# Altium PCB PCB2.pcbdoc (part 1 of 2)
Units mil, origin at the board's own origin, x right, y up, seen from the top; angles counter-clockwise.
Board outline 2299 x 1559.01 mil, 4 copper layers (Top Layer, Inner1, Inner2, Bottom Layer); 35 components, 78 nets, 930 pads, 283 vias.
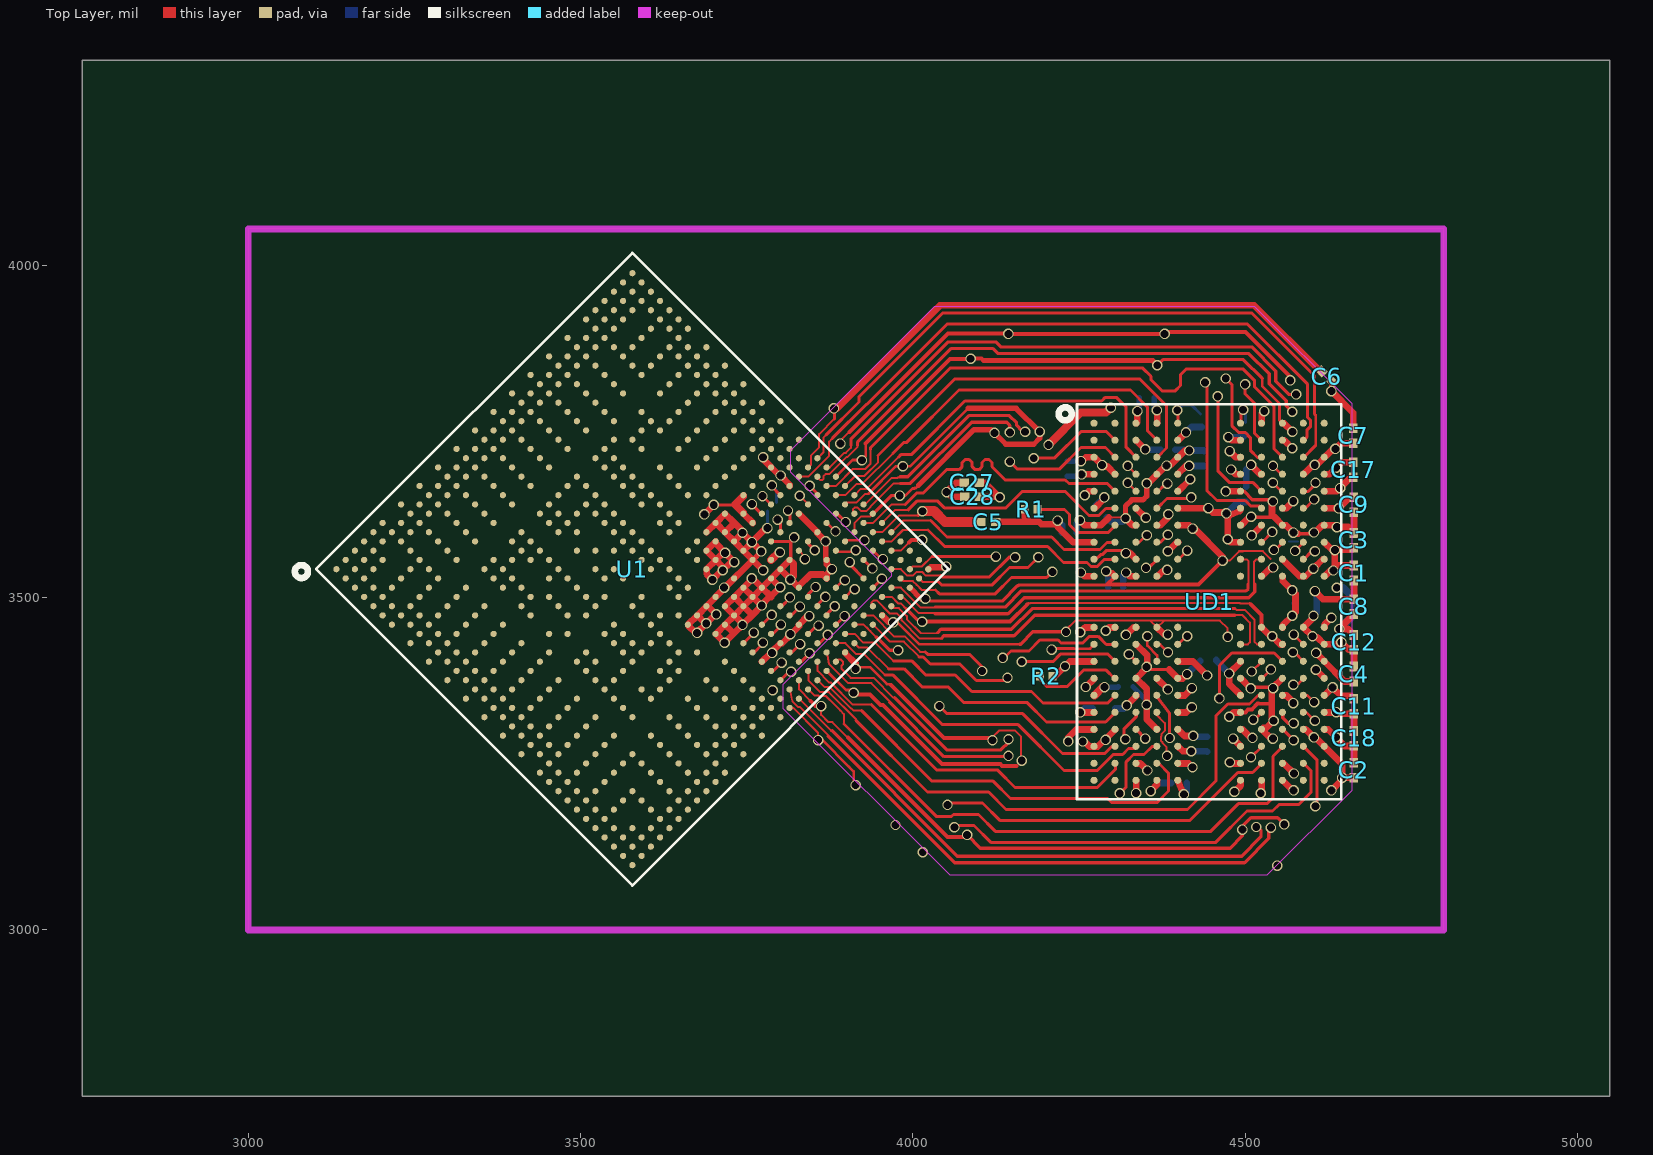
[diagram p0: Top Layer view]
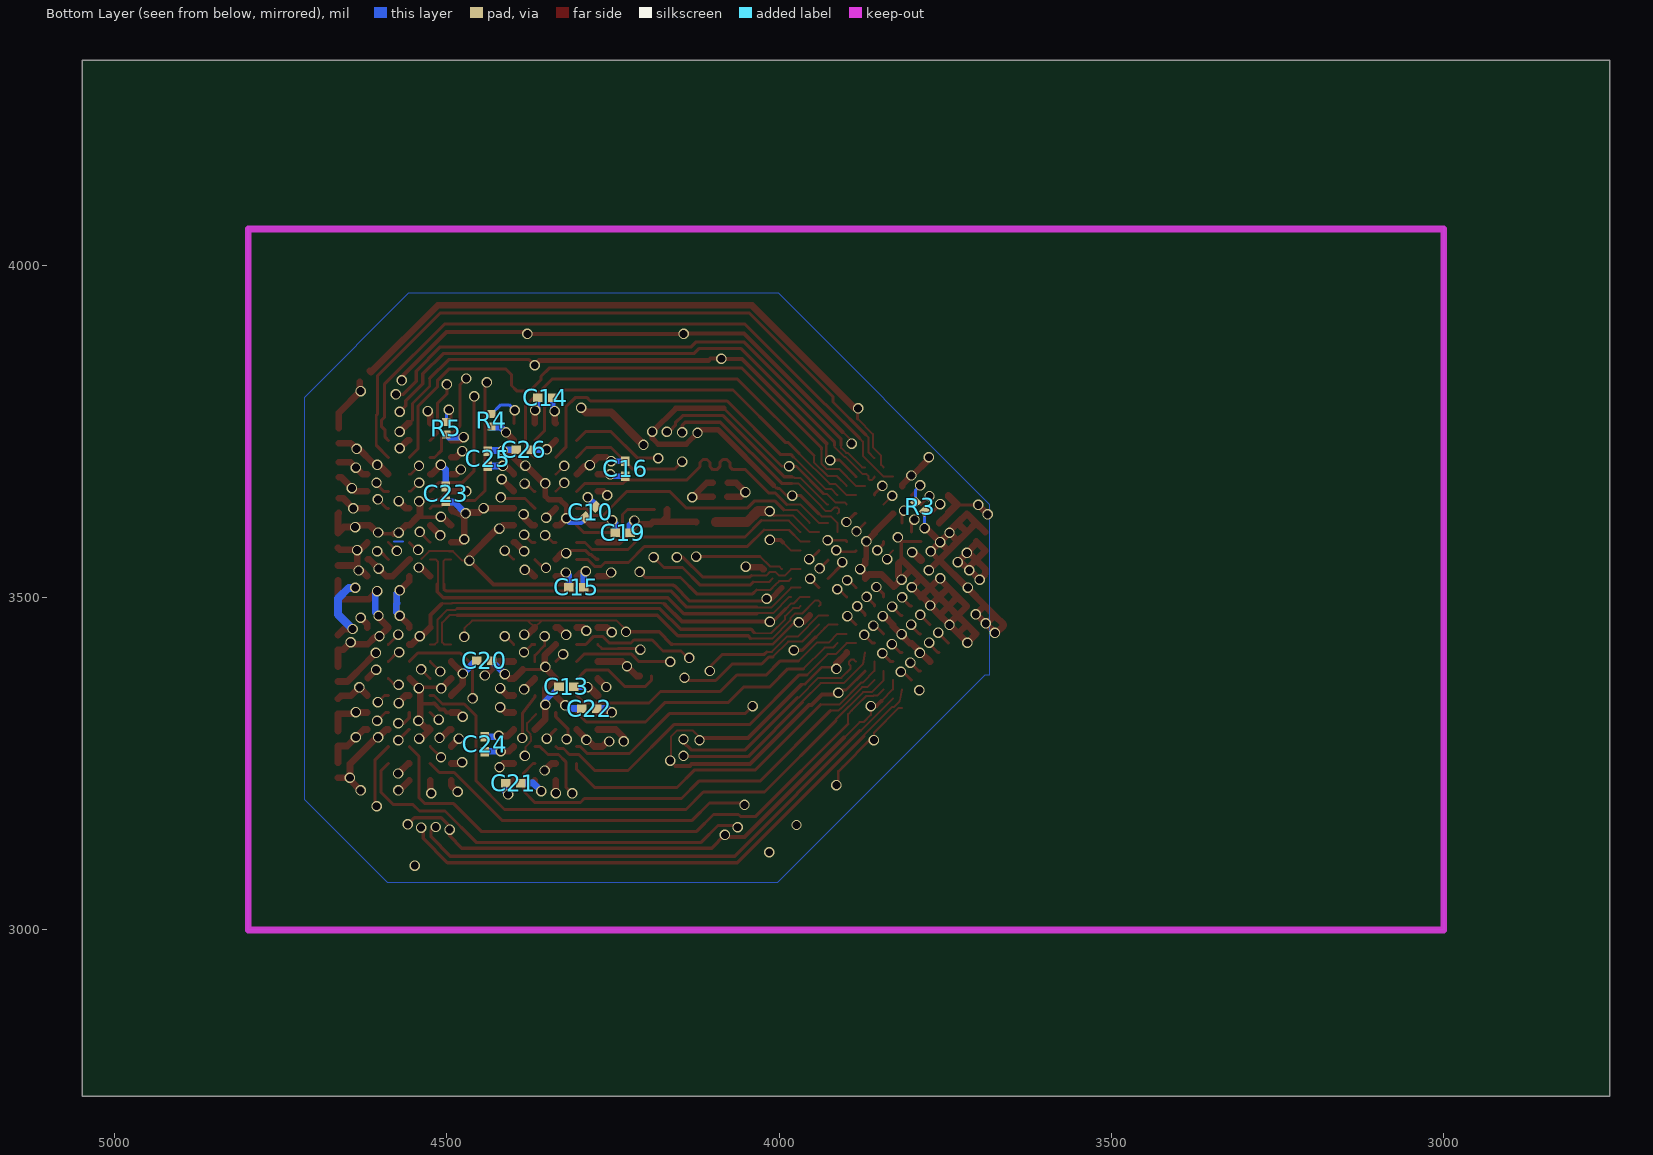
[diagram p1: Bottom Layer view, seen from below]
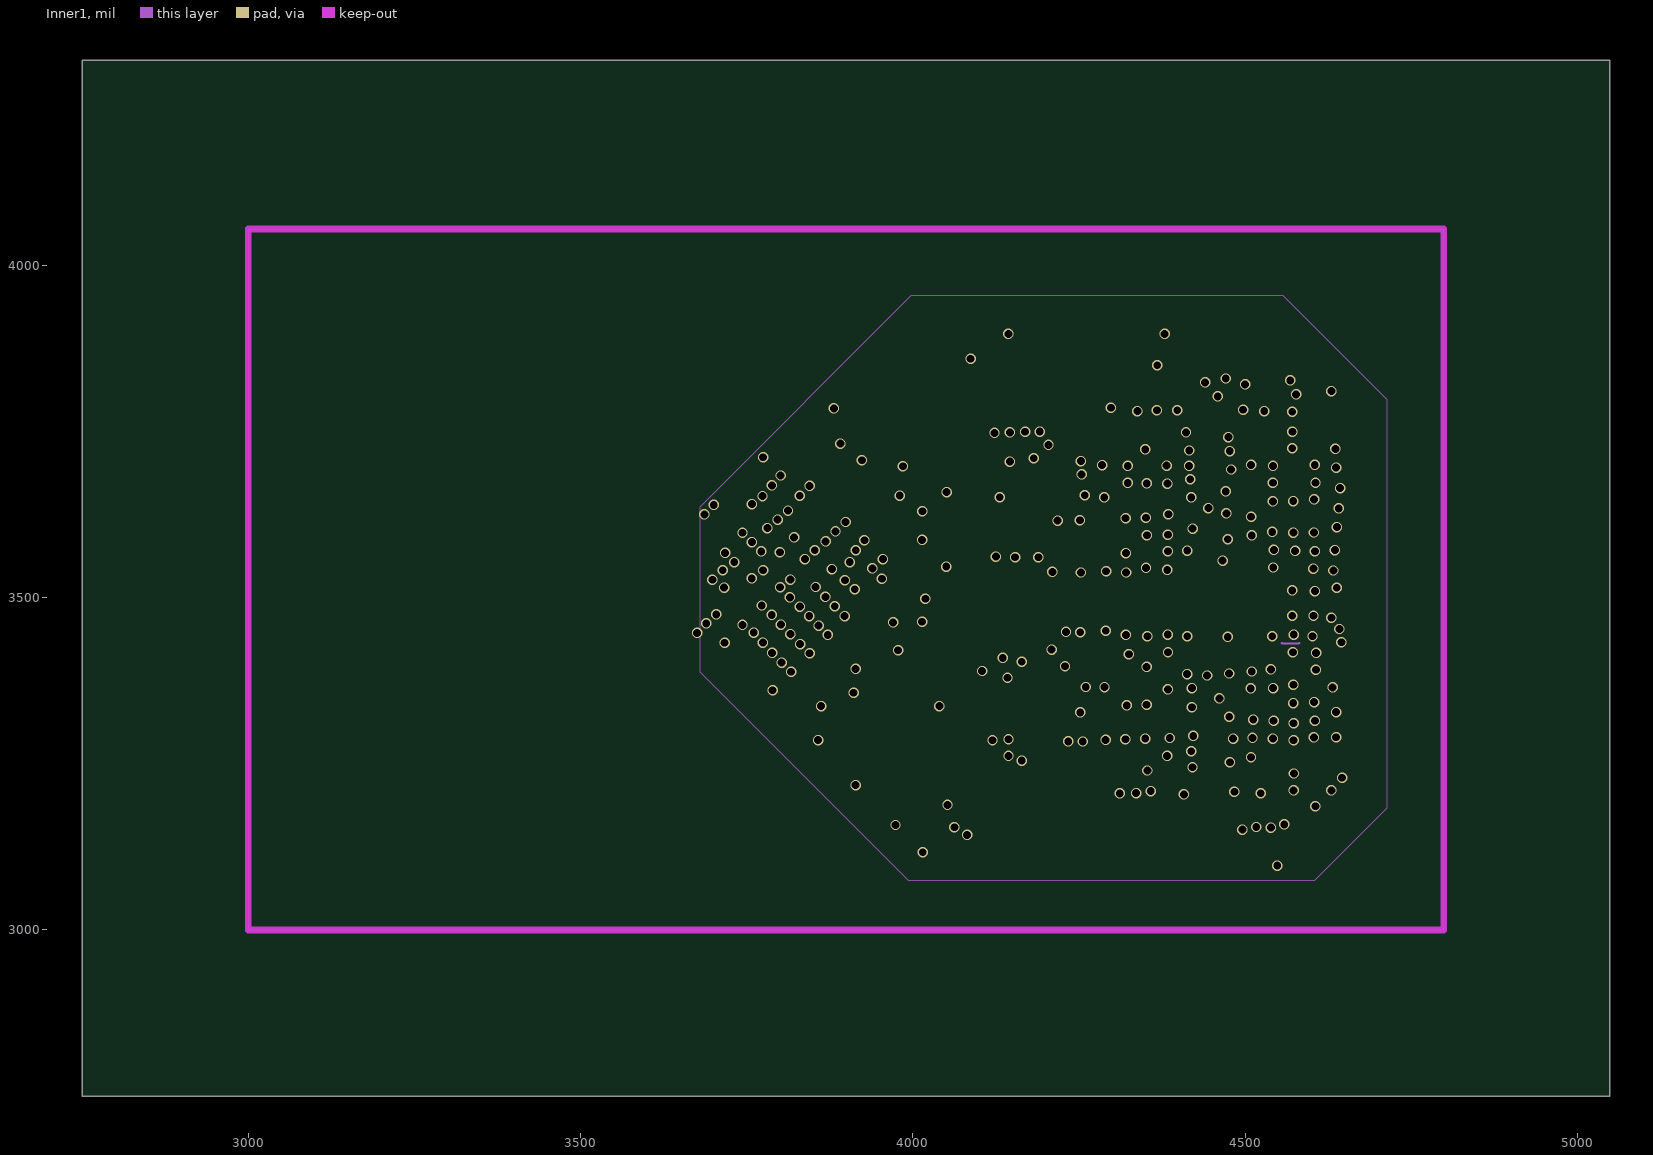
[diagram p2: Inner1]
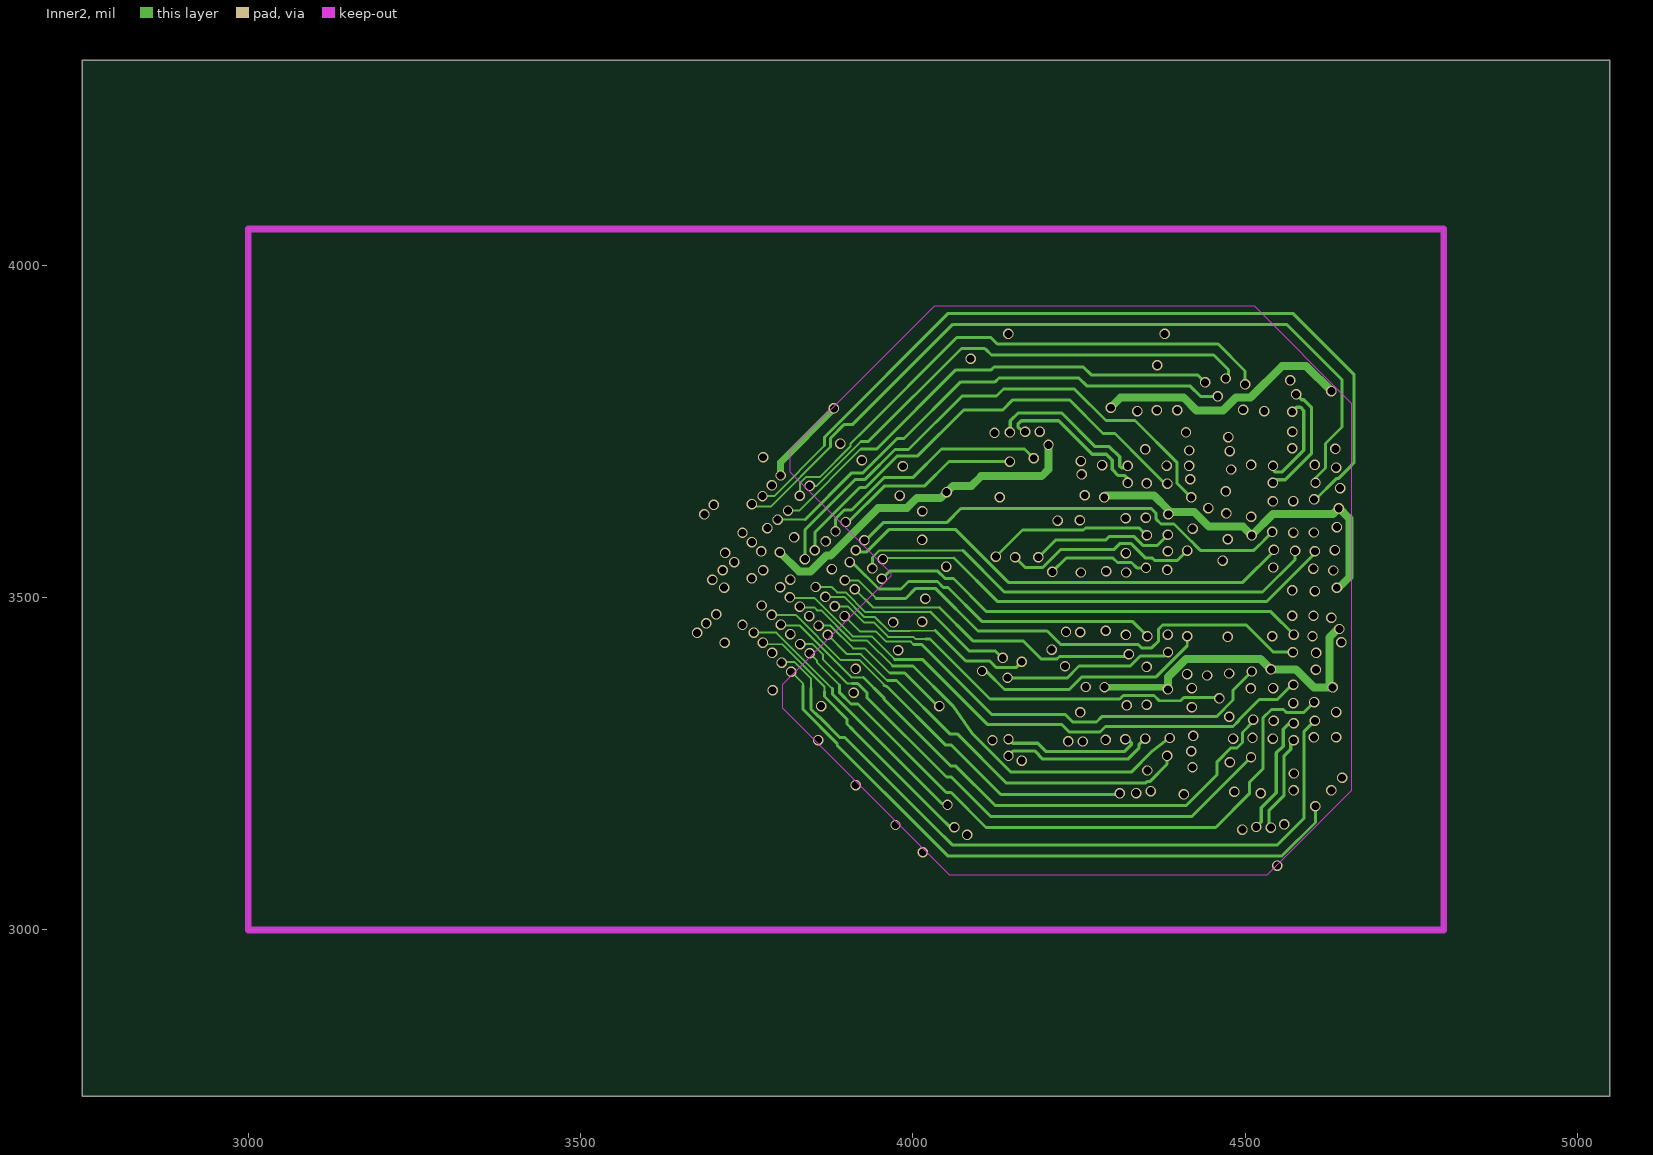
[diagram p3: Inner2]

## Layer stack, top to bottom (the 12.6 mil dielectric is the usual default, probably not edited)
Top Layer: signal copper (thickness not stored)
Dielectric: dielectric 12.6, FR-4, Dk 4.8
Inner1: signal copper (thickness not stored)
Dielectric: dielectric 12.6, FR-4, Dk 4.8
Inner2: signal copper (thickness not stored)
Dielectric: dielectric 12.6, FR-4, Dk 4.8
Bottom Layer: signal copper (thickness not stored)

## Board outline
5049,2750 2750,2750 2750,4309.01 5049,4309.01

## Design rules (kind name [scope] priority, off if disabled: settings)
Clearance safeClearance [All] p1: gap=7 ignorepadtopadclearanceinfootprint=FALSE except(3: Track-Track Track-SMDPad Track-THPad Track-Hole; 3.5: SMDPad-SMDPad SMDPad-THPad THPad-THPad Track-Via SMDPad-Via THPad-Via Via-Via Track-Fill SMDPad-Fill THPad-Fill Via-Fill Fill-Fill Track-Region SMDPad-Region THPad-Region Via-Region Fill-Region Region-Region Track-Poly SMDPad-Poly THPad-Poly Via-Poly Fill-Poly Region-Poly Poly-Poly Track-Text SMDPad-Text THPad-Text Via-Text Fill-Text Region-Text Poly-Text Text-Text SMDPad-Sheet THPad-Sheet SMDPad-Hole THPad-Hole Via-Hole Fill-Hole Region-Hole Poly-Hole Text-Hole Sheet-Hole; 11.8: Track-Sheet Via-Sheet Fill-Sheet Region-Sheet Poly-Sheet Text-Sheet)
DiffPairsRouting differentialPair [All] p1: maxuncoupledlength=50 minlimit=0 maxlimit=4 mostfreqgap=4 toplayer_minwidth=4 toplayer_prefwidth=10 toplayer_maxwidth=100 bottomlayer_minwidth=4 bottomlayer_prefwidth=10 bottomlayer_maxwidth=100 midlayer1_minwidth=4 midlayer1_prefwidth=10 midlayer1_maxwidth=100 midlayer2_minwidth=4 midlayer2_prefwidth=10 midlayer2_maxwidth=100
PasteMaskExpansion pasteMaskExpansion [All] p1: expansion=0
PlaneConnect innerPlane [All] p1: planeconnectstyle=Relief reliefexpansion=20 reliefentries=4 reliefconductorwidth=10 reliefairgap=10
PolygonConnect copperRegion [All] p1: connectstyle=Relief reliefentries=4 reliefconductorwidth=10 polygonreliefangle="90 Angle" airgapwidth=10
PolygonConnect TBCopper [All] p1: connectstyle=Relief reliefentries=4 reliefconductorwidth=6 polygonreliefangle="90 Angle" airgapwidth=6
PolygonConnect DRAMCopper [All] p1: connectstyle=Relief reliefentries=4 reliefconductorwidth=4 polygonreliefangle="90 Angle" airgapwidth=4
RoutingVias viaSize [All] p1: viastyle="Through Hole" holewidth=7.9 minholewidth=7.9 maxholewidth=236.2 width=17.7 minwidth=15 maxwidth=393.7
SolderMaskExpansion solderMaskExpansion [All] p1: useseparateexpansions=TRUE expansion=4 expansionbottom=4
Width trackWidth [All] p1: maxlimit=100 minlimit=3 preferedwidth=4

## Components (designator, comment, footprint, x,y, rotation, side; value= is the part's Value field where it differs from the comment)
C1 "0201X225M6R3NT" "c0201 nsk" 4664,3537 r270 top
C2 "0201X225M6R3NT" "c0201 nsk" 4664,3240 r270 top
C3 "GRM033R61A104KE15D" "c0201 nsk" 4664,3586 r270 top
C4 "GRM033R61A104KE15D" "c0201 nsk" 4664,3385 r270 top
C5 "GRM033R61A104KE15D" "c0201 nsk" 4114,3614 r0 top
C6 "0201X225M6R3NT" "c0201 nsk" 4623,3833 r135 top
C7 "GRM033R61A104KE15D" "c0201 nsk" 4663,3744 r90 top
C8 "0201X225M6R3NT" "c0201 nsk" 4664,3487 r90 top
C9 "GRM033R61A104KE15D" "c0201 nsk" 4664,3640 r90 top
C10 "GRM033R61A104KE15D" "c0201 nsk" 4284,3629 r135 bottom
C11 "GRM033R61A104KE15D" "c0201 nsk" 4664,3337 r90 top
C12 "GRM033R61A104KE15D" "c0201 nsk" 4664,3433 r90 top
C13 "GRM033R61A104KE15D" "c0201 nsk" 4320,3366 r180 bottom
C14 "0201X225M6R3NT" "c0201 nsk" 4352,3801 r180 bottom
C15 "0201X225M6R3NT" "c0201 nsk" 4305,3516 r180 bottom
C16 "GRM033R61A104KE15D" "c0201 nsk" 4232,3694 r270 bottom
C17 "GRM033R61A104KE15D" "c0201 nsk" 4663,3693 r90 top
C18 "GRM033R61A104KE15D" "c0201 nsk" 4664,3288 r270 top
C19 "0201X225M6R3NT" "c0201 nsk" 4236,3598 r0 bottom
C20 "GRM033R61A104KE15D" "c0201 nsk" 4444.09,3405.33 r0 bottom
C21 "GRM033R61A104KE15D" "c0201 nsk" 4400,3221 r180 bottom
C22 "GRM033R61A104KE15D" "c0201 nsk" 4286,3333 r0 bottom
C23 "GRM033R61A104KE15D" "c0201 nsk" 4502,3656 r270 bottom
C24 "GRM033R61A104KE15D" "c0201 nsk" 4443,3280 r90 bottom
C25 "GRM033R61A104KE15D" "c0201 nsk" 4439,3709 r270 bottom
C26 "GRM033R61A104KE15D" "c0201 nsk" 4384,3723 r180 bottom
C27 "0201X225M6R3NT" "c0201 nsk" 4089,3673 r0 top
C28 "GRM033R61A104KE15D" "c0201 nsk" 4089,3652 r180 top
R1 "Res_0201" "r0201 nsk" 4178,3633 r180 top
R2 "Res_0201" "r0201 nsk" 4201,3382 r0 top
R3 "Res_0201" "r0201 nsk" 3788,3637 r225 bottom
R4 "Res_0201" "r0201 nsk" 4433,3767 r270 bottom
R5 "Res_0201" "r0201 nsk" 4501,3755 r270 bottom
U1 "T527" T527-BGA664 3578,3543 r45 top
UD1 "LPDDR4_FBGA200" BGA200P65_80B1000_1500H90 4446,3494 r0 top

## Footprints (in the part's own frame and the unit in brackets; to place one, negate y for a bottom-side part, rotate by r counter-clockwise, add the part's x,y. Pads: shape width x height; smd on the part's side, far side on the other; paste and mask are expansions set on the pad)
BGA200P65_80B1000_1500H90 [mm]
  round 0.27 smd: A1(-4.4,6.825) A2(-3.6,6.825) A3(-2.8,6.825) A4(-2,6.825) A5(-1.2,6.825) A8(1.2,6.825) A9(2,6.825) A10(2.8,6.825) A11(3.6,6.825) A12(4.4,6.825) AA1(-4.4,-6.175) AA2(-3.6,-6.175) AA3(-2.8,-6.175) AA4(-2,-6.175) AA5(-1.2,-6.175) AA8(1.2,-6.175) AA9(2,-6.175) AA10(2.8,-6.175) AA11(3.6,-6.175) AA12(4.4,-6.175) AB1(-4.4,-6.825) AB2(-3.6,-6.825) AB3(-2.8,-6.825) AB4(-2,-6.825) AB5(-1.2,-6.825) AB8(1.2,-6.825) AB9(2,-6.825) AB10(2.8,-6.825) AB11(3.6,-6.825) AB12(4.4,-6.825) B1(-4.4,6.175) B2(-3.6,6.175) B3(-2.8,6.175) B4(-2,6.175) B5(-1.2,6.175) B8(1.2,6.175) B9(2,6.175) B10(2.8,6.175) B11(3.6,6.175) B12(4.4,6.175) C1(-4.4,5.525) C2(-3.6,5.525) C3(-2.8,5.525) C4(-2,5.525) C5(-1.2,5.525) C8(1.2,5.525) C9(2,5.525) C10(2.8,5.525) C11(3.6,5.525) C12(4.4,5.525) D1(-4.4,4.875) D2(-3.6,4.875) D3(-2.8,4.875) D4(-2,4.875) D5(-1.2,4.875) D8(1.2,4.875) D9(2,4.875) D10(2.8,4.875) D11(3.6,4.875) D12(4.4,4.875) E1(-4.4,4.225) E2(-3.6,4.225) E3(-2.8,4.225) E4(-2,4.225) E5(-1.2,4.225) E8(1.2,4.225) E9(2,4.225) E10(2.8,4.225) E11(3.6,4.225) E12(4.4,4.225) F1(-4.4,3.575) F2(-3.6,3.575) F3(-2.8,3.575) F4(-2,3.575) F5(-1.2,3.575) F8(1.2,3.575) F9(2,3.575) F10(2.8,3.575) F11(3.6,3.575) F12(4.4,3.575) G1(-4.4,2.925) G2(-3.6,2.925) G3(-2.8,2.925) G4(-2,2.925) G5(-1.2,2.925) G8(1.2,2.925) G9(2,2.925) G10(2.8,2.925) G11(3.6,2.925) G12(4.4,2.925) H1(-4.4,2.275) H2(-3.6,2.275) H3(-2.8,2.275) H4(-2,2.275) H5(-1.2,2.275) H8(1.2,2.275) H9(2,2.275) H10(2.8,2.275) H11(3.6,2.275) H12(4.4,2.275) J1(-4.4,1.625) J2(-3.6,1.625) J3(-2.8,1.625) J4(-2,1.625) J5(-1.2,1.625) J8(1.2,1.625) J9(2,1.625) J10(2.8,1.625) J11(3.6,1.625) J12(4.4,1.625) K1(-4.4,0.975) K2(-3.6,0.975) K3(-2.8,0.975) K4(-2,0.975) K5(-1.2,0.975) K8(1.2,0.975) K9(2,0.975) K10(2.8,0.975) K11(3.6,0.975) K12(4.4,0.975) N1(-4.4,-0.975) N2(-3.6,-0.975) N3(-2.8,-0.975) N4(-2,-0.975) N5(-1.2,-0.975) N8(1.2,-0.975) N9(2,-0.975) N10(2.8,-0.975) N11(3.6,-0.975) N12(4.4,-0.975) P1(-4.4,-1.625) P2(-3.6,-1.625) P3(-2.8,-1.625) P4(-2,-1.625) P5(-1.2,-1.625) P8(1.2,-1.625) P9(2,-1.625) P10(2.8,-1.625) P11(3.6,-1.625) P12(4.4,-1.625) R1(-4.4,-2.275) R2(-3.6,-2.275) R3(-2.8,-2.275) R4(-2,-2.275) R5(-1.2,-2.275) R8(1.2,-2.275) R9(2,-2.275) R10(2.8,-2.275) R11(3.6,-2.275) R12(4.4,-2.275) T1(-4.4,-2.925) T2(-3.6,-2.925) T3(-2.8,-2.925) T4(-2,-2.925) T5(-1.2,-2.925) T8(1.2,-2.925) T9(2,-2.925) T10(2.8,-2.925) T11(3.6,-2.925) T12(4.4,-2.925) U1(-4.4,-3.575) U2(-3.6,-3.575) U3(-2.8,-3.575) U4(-2,-3.575) U5(-1.2,-3.575) U8(1.2,-3.575) U9(2,-3.575) U10(2.8,-3.575) U11(3.6,-3.575) U12(4.4,-3.575) V1(-4.4,-4.225) V2(-3.6,-4.225) V3(-2.8,-4.225) V4(-2,-4.225) V5(-1.2,-4.225) V8(1.2,-4.225) V9(2,-4.225) V10(2.8,-4.225) V11(3.6,-4.225) V12(4.4,-4.225) W1(-4.4,-4.875) W2(-3.6,-4.875) W3(-2.8,-4.875) W4(-2,-4.875) W5(-1.2,-4.875) W8(1.2,-4.875) W9(2,-4.875) W10(2.8,-4.875) W11(3.6,-4.875) W12(4.4,-4.875) Y1(-4.4,-5.525) Y2(-3.6,-5.525) Y3(-2.8,-5.525) Y4(-2,-5.525) Y5(-1.2,-5.525) Y8(1.2,-5.525) Y9(2,-5.525) Y10(2.8,-5.525) Y11(3.6,-5.525) Y12(4.4,-5.525)
  silkscreen extent -5.75,-7.55 5.05,7.55
"c0201 nsk" [mil]
  rect 14.51x12.76 smd: 1(-11.5,0) 2(11,0)
"r0201 nsk" [mil]
  rect 11.93x12.76 smd: 1(-9.51,0) 2(9.51,0)
T527-BGA664 [mm]
  round 0.239 smd: A1(-8,8) A2(-7.5,8) A3(-7,8) A4(-6.5,8) A5(-6,8) A6(-5.5,8) A8(-4.5,8) A10(-3.5,8) A12(-2.5,8) A14(-1.5,8) A16(-0.5,8) A18(0.5,8) A20(1.5,8) A22(2.5,8) A24(3.5,8) A26(4.5,8) A28(5.5,8) A29(6,8) A30(6.5,8) A31(7,8) A32(7.5,8) A33(8,8) AA1(-8,-2) AA2(-7.5,-2) AA3(-7,-2) AA4(-6.5,-2) AA5(-6,-2) AA6(-5.5,-2) AA7(-5,-2) AA9(-4,-2) AA12(-2.5,-2) AA13(-2,-2) AA15(-1,-2) AA16(-0.5,-2) AA18(0.5,-2) AA19(1,-2) AA21(2,-2) AA22(2.5,-2) AA24(3.5,-2) AA26(4.5,-2) AA27(5,-2) AA28(5.5,-2) AA29(6,-2) AA30(6.5,-2) AA31(7,-2) AA32(7.5,-2) AA33(8,-2) AB2(-7.5,-2.5) AB3(-7,-2.5) AB9(-4,-2.5) AB10(-3.5,-2.5) AB11(-3,-2.5) AB12(-2.5,-2.5) AB13(-2,-2.5) AB14(-1.5,-2.5) AB15(-1,-2.5) AB17(0,-2.5) AB24(3.5,-2.5) AB32(7.5,-2.5) AB33(8,-2.5) AC1(-8,-3) AC2(-7.5,-3) AC3(-7,-3) AC4(-6.5,-3) AC5(-6,-3) AC6(-5.5,-3) AC7(-5,-3) AC9(-4,-3) AC15(-1,-3) AC17(0,-3) AC18(0.5,-3) AC19(1,-3) AC20(1.5,-3) AC22(2.5,-3) AC24(3.5,-3) AC26(4.5,-3) AC27(5,-3) AC28(5.5,-3) AC29(6,-3) AC30(6.5,-3) AC31(7,-3) AC32(7.5,-3) AC33(8,-3) AD1(-8,-3.5) AD2(-7.5,-3.5) AD9(-4,-3.5) AD11(-3,-3.5) AD13(-2,-3.5) AD14(-1.5,-3.5) AD15(-1,-3.5) AD20(1.5,-3.5) AD21(2,-3.5) AD22(2.5,-3.5) AD25(4,-3.5) AD32(7.5,-3.5) AD33(8,-3.5) AE1(-8,-4) AE2(-7.5,-4) AE3(-7,-4) AE4(-6.5,-4) AE5(-6,-4) AE6(-5.5,-4) AE7(-5,-4) AE9(-4,-4) AE11(-3,-4) AE12(-2.5,-4) AE13(-2,-4) AE14(-1.5,-4) AE16(-0.5,-4) AE18(0.5,-4) AE19(1,-4) AE20(1.5,-4) AE21(2,-4) AE22(2.5,-4) AE23(3,-4) AE24(3.5,-4) AE25(4,-4) AE26(4.5,-4) AE27(5,-4) AE28(5.5,-4) AE29(6,-4) AE30(6.5,-4) AE31(7,-4) AE32(7.5,-4) AE33(8,-4) AF1(-8,-4.5) AF2(-7.5,-4.5) AF32(7.5,-4.5) AF33(8,-4.5) AG1(-8,-5) AG2(-7.5,-5) AG3(-7,-5) AG4(-6.5,-5) AG5(-6,-5) AG6(-5.5,-5) AG7(-5,-5) AG9(-4,-5) AG11(-3,-5) AG13(-2,-5) AG15(-1,-5) AG17(0,-5) AG19(1,-5) AG21(2,-5) AG23(3,-5) AG25(4,-5) AG28(5.5,-5) AG29(6,-5) AG30(6.5,-5) AG31(7,-5) AG32(7.5,-5) AG33(8,-5) AH1(-8,-5.5) AH2(-7.5,-5.5) AH7(-5,-5.5) AH9(-4,-5.5) AH11(-3,-5.5) AH13(-2,-5.5) AH15(-1,-5.5) AH17(0,-5.5) AH19(1,-5.5) AH21(2,-5.5) AH23(3,-5.5) AH25(4,-5.5) AH27(5,-5.5) AH32(7.5,-5.5) AH33(8,-5.5) AJ1(-8,-6) AJ2(-7.5,-6) AJ3(-7,-6) AJ4(-6.5,-6) AJ5(-6,-6) AJ7(-5,-6) AJ9(-4,-6) AJ11(-3,-6) AJ13(-2,-6) AJ15(-1,-6) AJ17(0,-6) AJ19(1,-6) AJ21(2,-6) AJ23(3,-6) AJ25(4,-6) AJ27(5,-6) AJ30(6.5,-6) AJ31(7,-6) AJ32(7.5,-6) AJ33(8,-6) AK1(-8,-6.5) AK2(-7.5,-6.5) AK5(-6,-6.5) AK7(-5,-6.5) AK9(-4,-6.5) AK11(-3,-6.5) AK13(-2,-6.5) AK15(-1,-6.5) AK17(0,-6.5) AK19(1,-6.5) AK21(2,-6.5) AK23(3,-6.5) AK25(4,-6.5) AK27(5,-6.5) AK29(6,-6.5) AK32(7.5,-6.5) AK33(8,-6.5) AL1(-8,-7) AL2(-7.5,-7) AL3(-7,-7) AL5(-6,-7) AL7(-5,-7) AL9(-4,-7) AL11(-3,-7) AL12(-2.5,-7) AL13(-2,-7) AL14(-1.5,-7) AL15(-1,-7) AL16(-0.5,-7) AL17(0,-7) AL19(1,-7) AL21(2,-7) AL23(3,-7) AL25(4,-7) AL27(5,-7) AL29(6,-7) AL31(7,-7) AL32(7.5,-7) AL33(8,-7) AM1(-8,-7.5) AM2(-7.5,-7.5) AM3(-7,-7.5) AM4(-6.5,-7.5) AM5(-6,-7.5) AM6(-5.5,-7.5) AM7(-5,-7.5) AM8(-4.5,-7.5) AM9(-4,-7.5) AM10(-3.5,-7.5) AM11(-3,-7.5) AM12(-2.5,-7.5) AM13(-2,-7.5) AM14(-1.5,-7.5) AM15(-1,-7.5) AM16(-0.5,-7.5) AM17(0,-7.5) AM18(0.5,-7.5) AM19(1,-7.5) AM20(1.5,-7.5) AM21(2,-7.5) AM22(2.5,-7.5) AM23(3,-7.5) AM24(3.5,-7.5) AM25(4,-7.5) AM26(4.5,-7.5) AM27(5,-7.5) AM28(5.5,-7.5) AM29(6,-7.5) AM30(6.5,-7.5) AM31(7,-7.5) AM32(7.5,-7.5) AM33(8,-7.5) AN1(-8,-8) AN2(-7.5,-8) AN3(-7,-8) AN4(-6.5,-8) AN5(-6,-8) AN6(-5.5,-8) AN7(-5,-8) AN8(-4.5,-8) AN9(-4,-8) AN10(-3.5,-8) AN11(-3,-8) AN13(-2,-8) AN15(-1,-8) AN17(0,-8) AN18(0.5,-8) AN19(1,-8) AN20(1.5,-8) AN21(2,-8) AN22(2.5,-8) AN23(3,-8) AN24(3.5,-8) AN25(4,-8) AN26(4.5,-8) AN27(5,-8) AN28(5.5,-8) AN29(6,-8) AN30(6.5,-8) AN31(7,-8) AN32(7.5,-8) AN33(8,-8) B1(-8,7.5) B2(-7.5,7.5) B3(-7,7.5) B4(-6.5,7.5) B5(-6,7.5) B6(-5.5,7.5) B7(-5,7.5) B8(-4.5,7.5) B9(-4,7.5) B10(-3.5,7.5) B11(-3,7.5) B12(-2.5,7.5) B13(-2,7.5) B14(-1.5,7.5) B15(-1,7.5) B16(-0.5,7.5) B17(0,7.5) B18(0.5,7.5) B19(1,7.5) B20(1.5,7.5) B21(2,7.5) B22(2.5,7.5) B23(3,7.5) B24(3.5,7.5) B25(4,7.5) B26(4.5,7.5) B27(5,7.5) B28(5.5,7.5) B29(6,7.5) B30(6.5,7.5) B31(7,7.5) B32(7.5,7.5) B33(8,7.5) C1(-8,7) C2(-7.5,7) C3(-7,7) C4(-6.5,7) C6(-5.5,7) C7(-5,7) C8(-4.5,7) C9(-4,7) C10(-3.5,7) C11(-3,7) C12(-2.5,7) C13(-2,7) C14(-1.5,7) C15(-1,7) C16(-0.5,7) C17(0,7) C18(0.5,7) C19(1,7) C20(1.5,7) C21(2,7) C22(2.5,7) C23(3,7) C24(3.5,7) C25(4,7) C26(4.5,7) C27(5,7) C28(5.5,7) C29(6,7) C30(6.5,7) C31(7,7) C32(7.5,7) C33(8,7) D1(-8,6.5) D2(-7.5,6.5) D6(-5.5,6.5) D8(-4.5,6.5) D10(-3.5,6.5) D12(-2.5,6.5) D14(-1.5,6.5) D16(-0.5,6.5) D18(0.5,6.5) D20(1.5,6.5) D22(2.5,6.5) D24(3.5,6.5) D26(4.5,6.5) D28(5.5,6.5) D32(7.5,6.5) D33(8,6.5) E1(-8,6) E2(-7.5,6) E3(-7,6) E4(-6.5,6) E5(-6,6) E6(-5.5,6) E8(-4.5,6) E10(-3.5,6) E12(-2.5,6) E14(-1.5,6) E16(-0.5,6) E18(0.5,6) E20(1.5,6) E22(2.5,6) E24(3.5,6) E26(4.5,6) E28(5.5,6) E29(6,6) E30(6.5,6) E31(7,6) E32(7.5,6) E33(8,6) F1(-8,5.5) F2(-7.5,5.5) F6(-5.5,5.5) F8(-4.5,5.5) F10(-3.5,5.5) F12(-2.5,5.5) F14(-1.5,5.5) F16(-0.5,5.5) F18(0.5,5.5) F20(1.5,5.5) F22(2.5,5.5) F24(3.5,5.5) F26(4.5,5.5) F28(5.5,5.5) F32(7.5,5.5) F33(8,5.5) G1(-8,5) G2(-7.5,5) G3(-7,5) G4(-6.5,5) G5(-6,5) G6(-5.5,5) G8(-4.5,5) G10(-3.5,5) G12(-2.5,5) G14(-1.5,5) G16(-0.5,5) G18(0.5,5) G20(1.5,5) G22(2.5,5) G24(3.5,5) G26(4.5,5) G28(5.5,5) G29(6,5) G30(6.5,5) G31(7,5) G32(7.5,5) G33(8,5) H2(-7.5,4.5) H3(-7,4.5) H24(3.5,4.5) H31(7,4.5) H32(7.5,4.5) J1(-8,4) J2(-7.5,4) J3(-7,4) J4(-6.5,4) J5(-6,4) J6(-5.5,4) J7(-5,4) J9(-4,4) J10(-3.5,4) J12(-2.5,4) J13(-2,4) J15(-1,4) J16(-0.5,4) J17(0,4) J18(0.5,4) J19(1,4) J21(2,4) J22(2.5,4) J23(3,4) J26(4.5,4) J28(5.5,4) J29(6,4) J30(6.5,4) J31(7,4) J32(7.5,4) J33(8,4) K2(-7.5,3.5) K3(-7,3.5) K9(-4,3.5) K10(-3.5,3.5) K11(-3,3.5) K12(-2.5,3.5) K13(-2,3.5) K15(-1,3.5) K16(-0.5,3.5) K19(1,3.5) K21(2,3.5) K22(2.5,3.5) K24(3.5,3.5) K25(4,3.5) K26(4.5,3.5) K31(7,3.5) K32(7.5,3.5) L1(-8,3) L2(-7.5,3) L3(-7,3) L4(-6.5,3) L5(-6,3) L6(-5.5,3) L7(-5,3) L9(-4,3) L10(-3.5,3) L12(-2.5,3) L13(-2,3) L15(-1,3) L16(-0.5,3) L17(0,3) L18(0.5,3) L19(1,3) L21(2,3) L22(2.5,3) L24(3.5,3) L26(4.5,3) L27(5,3) L28(5.5,3) L29(6,3) L30(6.5,3) L31(7,3) L32(7.5,3) L33(8,3) M2(-7.5,2.5) M3(-7,2.5) M10(-3.5,2.5) M13(-2,2.5) M16(-0.5,2.5) M18(0.5,2.5) M19(1,2.5) M21(2,2.5) M22(2.5,2.5) M31(7,2.5) M32(7.5,2.5) N1(-8,2) N2(-7.5,2) N3(-7,2) N4(-6.5,2) N5(-6,2) N6(-5.5,2) N7(-5,2) N9(-4,2) N10(-3.5,2) N12(-2.5,2) N13(-2,2) N15(-1,2) N18(0.5,2) N19(1,2) N21(2,2) N22(2.5,2) N24(3.5,2) N26(4.5,2) N27(5,2) N28(5.5,2) N29(6,2) N30(6.5,2) N31(7,2) N32(7.5,2) N33(8,2) P2(-7.5,1.5) P3(-7,1.5) P9(-4,1.5) P11(-3,1.5) P13(-2,1.5) P16(-0.5,1.5) P18(0.5,1.5) P19(1,1.5) P21(2,1.5) P22(2.5,1.5) P24(3.5,1.5) P31(7,1.5) P32(7.5,1.5) R1(-8,1) R2(-7.5,1) R3(-7,1) R4(-6.5,1) R5(-6,1) R6(-5.5,1) R7(-5,1) R11(-3,1) R13(-2,1) R15(-1,1) R17(0,1) R18(0.5,1) R19(1,1) R22(2.5,1) R24(3.5,1) R26(4.5,1) R27(5,1) R28(5.5,1) R29(6,1) R30(6.5,1) R31(7,1) R32(7.5,1) R33(8,1) T2(-7.5,0.5) T3(-7,0.5) T9(-4,0.5) T11(-3,0.5) T13(-2,0.5) T15(-1,0.5) T16(-0.5,0.5) T18(0.5,0.5) T19(1,0.5) T21(2,0.5) T22(2.5,0.5) T24(3.5,0.5) T31(7,0.5) T32(7.5,0.5) U1(-8,0) U2(-7.5,0) U3(-7,0) U4(-6.5,0) U5(-6,0) U6(-5.5,0) U7(-5,0) U8(-4.5,0) U10(-3.5,0) U12(-2.5,0) U13(-2,0) U14(-1.5,0) U16(-0.5,0) U18(0.5,0) U19(1,0) U21(2,0) U22(2.5,0) U25(4,0) U26(4.5,0) U27(5,0) U28(5.5,0) U29(6,0) U30(6.5,0) U31(7,0) U32(7.5,0) U33(8,0) V2(-7.5,-0.5) V3(-7,-0.5) V18(0.5,-0.5) V19(1,-0.5) V31(7,-0.5) V32(7.5,-0.5) W1(-8,-1) W2(-7.5,-1) W3(-7,-1) W4(-6.5,-1) W5(-6,-1) W6(-5.5,-1) W7(-5,-1) W9(-4,-1) W10(-3.5,-1) W12(-2.5,-1) W13(-2,-1) W15(-1,-1) W16(-0.5,-1) W19(1,-1) W21(2,-1) W22(2.5,-1) W23(3,-1) W24(3.5,-1) W25(4,-1) W27(5,-1) W28(5.5,-1) W29(6,-1) W30(6.5,-1) W31(7,-1) W32(7.5,-1) W33(8,-1) Y2(-7.5,-1.5) Y3(-7,-1.5) Y9(-4,-1.5) Y10(-3.5,-1.5) Y12(-2.5,-1.5) Y13(-2,-1.5) Y15(-1,-1.5) Y18(0.5,-1.5) Y19(1,-1.5) Y21(2,-1.5) Y22(2.5,-1.5) Y23(3,-1.5) Y24(3.5,-1.5) Y26(4.5,-1.5) Y31(7,-1.5) Y32(7.5,-1.5)
  silkscreen extent -9.26,-8.55 8.55,9.13

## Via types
v1: diameter 15.75, hole 11.81, Top Layer to Bottom Layer, 283 vias

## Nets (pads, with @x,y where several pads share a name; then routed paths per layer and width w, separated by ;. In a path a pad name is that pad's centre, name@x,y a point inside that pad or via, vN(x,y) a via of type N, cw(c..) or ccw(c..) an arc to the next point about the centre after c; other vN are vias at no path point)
$2N2017: R3.1 U1.AA29 | length 48
  Top Layer w4.5: v1(3788,3669) 3788,3667.07 U1.AA29@3800.71,3654.36
  Bottom Layer w4.5: v1(3788,3669) 3794.72,3662.28 R3.1@3794.72,3643.72
$2N2070: R4.1 UD1.A5 | length 64.4
  Top Layer w4.5: v1(4398.05,3782.17) 4399.28,3780.94 UD1.A5@4399.28,3762.43
  Bottom Layer w4.5: v1(4398.05,3782.17) 4406.31,3790.43 4419.08,3790.43 R4.1@4433,3776.51
$2N2072: R5.1 UD1.A8 | length 43
  Top Layer w4.5: UD1.A8@4493.76,3762.43 4493.76,3779.68 v1(4497.08,3783)
  Bottom Layer w4.5: v1(4497.08,3783) 4500.71,3779.37 R5.1@4500.71,3763.41
$2N2081: R1.1 UD1.G2 | length 145
  Top Layer w4.5: R1.1@4187.51,3633 4228.31,3633 4236,3625.31 4236,3610 4247.68,3598.32 4294.22,3598.32 UD1.G2@4304.79,3608.89
$2N2083: R2.1 UD1.T2 | length 137.5
  Top Layer w4.5: R2.1@4192.49,3382 4192.2,3382.29 4192.2,3375.93 4201.94,3366.19 4232.13,3366.19 4256.94,3391 4291,3391 UD1.T2@4303.43,3378.57
GND: C1.2 C2.2 C3.1 C4.1 C5.1 C6.2 C7.1 C8.2 C9.1 C10.1 C11.1 C12.1 C13.1 C14.2 C15.2 C16.1 C17.1 C18.1 C19.2 C20.1 C21.1 C22.1 C23.1 C24.1 C25.1 C26.1 C27.2 C28.1 U1.A1 U1.AA15 U1.AA16 U1.AA18 U1.AA21 U1.AA22 U1.AA26 U1.AA30 U1.AA32 U1.AB10 U1.AB11 U1.AB12 U1.AB14 U1.AB15 U1.AB17 U1.AC1 U1.AC26 U1.AC29 U1.AC33 U1.AD9 U1.AD11 U1.AD13 U1.AD14 U1.AD20 U1.AD21 U1.AD22 U1.AE9 U1.AE12 U1.AE14 U1.AE18 U1.AE19 U1.AE20 U1.AE21 U1.AE22 U1.AE23 U1.AE24 U1.AE25 U1.AE26 U1.AE29 U1.AE32 U1.AG3 U1.AG6 U1.AG7 U1.AG11 U1.AG25 U1.AG28 U1.AG31 U1.AG33 U1.AH7 U1.AH9 U1.AH27 U1.AH32 U1.AJ13 U1.AJ19 U1.AJ21 U1.AJ23 U1.AK5 U1.AK11 U1.AK32 U1.AL3 U1.AL9 U1.AL12 U1.AL13 U1.AL14 U1.AM5 U1.AM20 U1.AM26 U1.AM29 U1.AN1 U1.AN10 U1.AN11 U1.AN18 U1.AN22 U1.AN24 U1.AN28 U1.AN31 U1.AN33 U1.C6 U1.C8 U1.C10 U1.C12 U1.C14 U1.C18 U1.C20 U1.D6 U1.E3 U1.F6 U1.F8 U1.F10 U1.F12 U1.G3 U1.G8 U1.G10 U1.G14 U1.G18 U1.G29 U1.J3 U1.J6 U1.J9 U1.J10 U1.J12 U1.J13 U1.J28 U1.J31 U1.K9 U1.K10 U1.K11 U1.K12 U1.K26 U1.L3 U1.L6 U1.L10 U1.L12 U1.L13 U1.L27 U1.L30 U1.L33 U1.M13 U1.N3 U1.N6 U1.N10 U1.N12 U1.N15 U1.N18 U1.N19 U1.N22 U1.N26 U1.N27 U1.N30 U1.P11 U1.P16 U1.P19 U1.P24 U1.R3 U1.R7 U1.R11 U1.R13 U1.R19 U1.R24 U1.R27 U1.T15 U1.T16 U1.T18 U1.T24 U1.U7 U1.U14 U1.U16 U1.U25 U1.U27 U1.V18 U1.V19 U1.W12 U1.W13 U1.W15 U1.W16 U1.W22 U1.W27 U1.W30 U1.Y15 U1.Y18 U1.Y22 U1.Y23 U1.Y26 UD1.A3 UD1.A10 UD1.AB3 UD1.AB5 UD1.AB8 UD1.AB10 UD1.C1 UD1.C5 UD1.C8 UD1.C12 UD1.D2 UD1.D4 UD1.D9 UD1.D11 UD1.E1 UD1.E5 UD1.E8 UD1.E12 UD1.G1 UD1.G3 UD1.G5 UD1.G8 UD1.G10 UD1.G12 UD1.J1 UD1.J3 UD1.J10 UD1.J12 UD1.K2 UD1.K4 UD1.K9 UD1.K11 UD1.N2 UD1.N4 UD1.N9 UD1.N11 UD1.P1 UD1.P3 UD1.P10 UD1.P12 UD1.T1 UD1.T3 UD1.T5 UD1.T8 UD1.T10 UD1.T12 UD1.V1 UD1.V5 UD1.V8 UD1.V12 UD1.W2 UD1.W4 UD1.W9 UD1.W11 UD1.Y1 UD1.Y5 UD1.Y8 UD1.Y12 | length 11800.7
  Top Layer w3: U1.AN18@3814.95,3334.21 3819.9,3334.21 3857.4,3296.71 v1(3857.4,3285.8) ; U1.AM20@3828.88,3375.97 3828.88,3362.07 3845.97,3344.98 ; U1.AA32@3842.79,3696.12 3846.6,3699.93 3846.6,3713.81 3859,3726.21 3859,3746.1 3882.1,3769.2 ; v1(3862,3337) 3862,3323.9 3873.2,3312.7 3879.12,3312.7 3902.25,3289.57 ; v1@3880.7,3779.2 3880.7,3782.39 3880.7,3783.49 3880.7,3784.9 v1(3881.25,3784.9) v1@3881.68,3784.47 ; v1(3891,3732) 3891,3736.13 3904.5,3749.63 ; U1.AE32@3898.47,3640.44 3901.43,3643.4 3915.39,3643.4 3928.3,3656.31 3932.99,3656.31 ; U1.AM26@3912.39,3459.48 3926.12,3459.48 3930.21,3455.39 3930.38,3455.39 3936.13,3449.64 3936.13,3449.47 3944.85,3440.75 ; U1.AG31@3912.39,3598.68 3912.39,3612.57 3922.24,3622.42 3936.13,3622.42 U1.AG33@3940.22,3626.51 ; U1.AH32@3940.23,3598.68 3954.13,3598.68 3979.45,3624 4008.18,3624 ; U1.AM29@3954.15,3501.24 3968.04,3501.24 3977.8,3491.48 3978.95,3491 3982.61,3491 3989.84,3483.77 ; U1.AK32@3968.07,3570.84 3982.01,3570.84 3994.58,3583.41 ; v1@4119,3289 4130.5,3300.5 4153.5,3300.5 4163,3291 4163,3256.08 v1(4164.08,3255) ; v1(4119.98,3285.49) v1@4123.47,3285.49 ; 4173.93,3491.67 4176.05,3491.67 4176.55,3492.17 4492.13,3492.17 4492.63,3491.67 4507.33,3491.67 ; v1(4230.6,3448.6) 4230.6,3451.7 4244.6,3465.7 4357.42,3465.7 ; 4295.08,3621 4318.78,3621 v1(4320.19,3619.59) ; v1(4466.3,3556) 4477.3,3556 4491.4,3570.1 4491.56,3570.1 ; v1(4474,3441) 4474,3454 4462.3,3465.7 4378.14,3465.7 ; 4496.4,3570.1 4526.76,3570.1 4538,3558.86 4538,3558 ; 4357.42,3465.7 4367.78,3455.34 4378.14,3465.7 ; 4357.42,3465.7 4378.14,3465.7
  Top Layer w4: v1(3857.4,3285.8) 3863.82,3285.8 3904.26,3245.36 3904.26,3245.24 3911,3238.5 3911,3221 v1(3914,3218) ; U1.AC33@3884.55,3682.19 3909.62,3707.26 3923.09,3707.26 v1(3923.32,3707.03) 3929,3712.71 3929,3731.99 ; v1@3910,3395.5 3914,3395.5 3935.5,3395.5 3961,3370 3966,3370 3967,3369 ; 3932.99,3656.31 3974.34,3697.66 3984.74,3697.66 v1(3985.08,3698) 3996.32,3698 4083.32,3785 ; v1(3970.3,3463) 3976.92,3463 4009.68,3430.2 4160.5,3430.2 ; v1(3980.4,3653.85) 3988.85,3653.85 3999.49,3664.49 4002.43,3664.49 4003.19,3665.25 4004.6,3665.25 4008.67,3669.32 ; 4172.26,3490 4173.93,3491.67 ; 4242.08,3423.5 4267.04,3423.5 UD1.P1@4273.29,3429.75 ; 4491.56,3570.1 4496.4,3570.1 ; 4507.33,3491.67 4509,3490 ; 4525.91,3830.01 4525.91,3818.45 4552,3792.36 4552,3767.19 UD1.A10@4556.76,3762.43
  Top Layer w4.5: U1.AN22@3870.63,3389.89 3899.52,3361 3907,3361 v1(3911,3357)
  Top Layer w5: v1(3700.57,3639.72) 3700.79,3639.51 3732.37,3639.51 ; U1.AC26@3787.11,3584.76 3815.4,3584.76 v1@3816.55,3585.91 ; U1.AE26@3814.95,3556.92 3816.55,3558.52 v1@3816.55,3585.91 ; v1(3821.5,3590.86) v1@3816.55,3585.91 ; v1@3881.68,3784.47 3880.7,3783.49 3880.15,3782.94 3880.7,3782.39 3882.1,3780.99 3882.1,3769.2 ; U1.AG33@3940.22,3626.52 3967.55,3653.85 v1(3980.4,3653.85) ; 3944.85,3440.75 3945.92,3440.75 3965.67,3421 v1(3978,3421) ; 3989.84,3483.77 4009.61,3464 v1(4014.08,3464) ; 4008.18,3624 v1(4014.46,3630.28) ; v1(4019.04,3498.41) 4022.45,3495 4134.6,3495 4157.5,3517.9 4158.43,3517.9 4159.7,3519.17 4296.17,3519.17 4296.67,3519.67 4297.12,3520.12 ; v1(4081.68,3143) 4101.47,3123.21 4477.61,3123.21 4496,3141.6 v1(4496,3151) 4496,3156 4509,3169 4549,3169 v1(4559,3159) ; 4160.5,3430.2 4162.3,3430.2 4180.7,3448.6 v1(4230.6,3448.6) ; v1(4208.96,3422) 4210.46,3423.5 4242.08,3423.5 ; UD1.J1@4273.29,3557.71 4275.71,3557.71 4282.98,3564.98 4285.03,3564.98 4291.05,3571 4316.95,3571 v1(4320.65,3567.3) ; v1(4352,3395.82) 4355.82,3392 4385.85,3392 ; v1(4368,3850) 4376.5,3858.5 4497.42,3858.5 4525.91,3830.01 ; UD1.E8@4493.76,3660.07 4498.58,3660.07 4510.99,3647.66 4537.42,3647.66 4540.08,3645 v1(4542.08,3645) ; v1(4508.67,3363.65) 4510.41,3365.39 4540.82,3365.39 v1(4542.2,3364.01) ; v1(4509.08,3622) 4509.78,3621.3 4544.35,3621.3 ; 4520.69,3340.57 4539.26,3340.57 4540.17,3341.47 ; v1@4580.13,3596.48 v1@4603.68,3596.48
  Top Layer w6: 3845.97,3344.98 3853.95,3337 v1(3862,3337) ; 3902.25,3289.57 4052.12,3139.7 4076.1,3139.7 4079.4,3143 v1(4081.68,3143) ; 3904.5,3749.63 4052.87,3898 4139,3898 4140,3897 v1(4144,3897) v1(4379,3897) 4382,3900 4500.95,3900 4568,3832.95 v1(4568,3827) ; v1(3911,3357) 3913.85,3354.15 3935.85,3354.15 3951.38,3338.62 3954.88,3338.62 4043.75,3249.75 4131.75,3249.75 4134.5,3247 4156.08,3247 ; 3929,3731.99 4056.01,3859 4086.25,3859 v1(4087,3859.75) 4103.81,3859.75 4106.56,3857 ; 3967,3369 4047,3289 v1@4119,3289 ; 3994.58,3583.41 3998.17,3587 v1(4014.08,3587) ; v1(4014.08,3464) 4146.26,3464 4172.26,3490 ; UD1.K2@4304.79,3532.12 4292.34,3519.67 4296.67,3519.67 4429.97,3519.67 v1(4466.3,3556) ; UD1.V8@4493.76,3327.39 4500.41,3327.39 4504.83,3331.81 4510.17,3331.81 4518.93,3340.57 4520.69,3340.57 ; 4509,3490 4525,3474 4525,3455.87 UD1.N9@4524.74,3455.61
  Top Layer w8: v1(3868.87,3584.92) 3868.87,3558.69 U1.AG28@3870.63,3556.92 ; U1.AN31@3995.9,3515.16 4012.65,3498.41 v1(4019.04,3498.41) ; 4008.67,3669.32 4092.35,3753 4118,3753 v1(4123,3748) 4140,3731 4182,3731 4191,3740 v1(4191,3750) 4190.62,3750 4155.62,3785 4083.32,3785 ; 4106.56,3857 4361,3857 v1(4368,3850) ; v1(4320.19,3619.59) 4320.19,3637.79 4329.74,3647.34 4346.42,3647.34 4352.08,3653 v1(4352.08,3672)
  Top Layer w10: v1@3686.44,3625.6 v1(3700.57,3639.72) ; 3758.48,3474.19 U1.AE21@3745.35,3487.32 ; U1.AA26@3759.28,3612.6 U1.Y26@3745.36,3626.52 ; U1.AJ19@3773.19,3403.81 3785.88,3416.5 3787.75,3416.5 v1(3788.35,3417.1) 3788.35,3418.96 3801.03,3431.64 3803.49,3431.64 3815.8,3443.95 v1(3815.8,3445.3) 3817.15,3445.3 3828.87,3457.02 3828.87,3459.48 3841.81,3472.42 v1(3844.26,3472.42) ; v1(3774.66,3711.49) 3774.66,3708.57 3799.68,3683.55 v1@3801.45,3683.55 ; v1(3801,3684) v1@3801.45,3683.55 ; v1@3801.8,3683.55 v1@3801.45,3683.55 ; U1.AA30@3814.95,3668.28 3814.95,3670.05 v1@3801.45,3683.55 ; U1.AC29@3828.87,3626.52 3856.71,3598.68 3856.71,3597.08 v1(3868.87,3584.92) ; U1.AG28@3870.63,3556.92 3870.63,3550.73 v1(3878.25,3543.11) 3870.63,3535.49 3870.63,3529.08 3864.71,3535 3846,3535 3827.51,3516.51 3816.73,3527.3 v1(3815.84,3527.3) ; v1(3881.25,3784.9) 3885.9,3784.9 4041,3940 4514,3940 4614.3,3839.7 C6.2@4616.38,3841.78 ; U1.AN24@3898.47,3417.73 3898.47,3416.53 3914,3401 3914,3395.5 v1(3914,3393) ; U1.AN28@3954.15,3473.41 3963.57,3463.99 3966.01,3463.99 3967,3463 v1(3970.3,3463) ; U1.AN33@4023.74,3543 4024.12,3543.38 4024.68,3543.38 4027.3,3546 4043.9,3546 4044.8,3546.9 v1(4050.4,3546.9) ; C27.2@4100,3673 4109.08,3673 v1@4130.08,3652 ; C28.1@4100.5,3652 v1@4130.08,3652 ; v1(4130.79,3651.29) v1@4130.08,3652 ; v1(4251.48,3616.54) 4259.13,3608.89 4282.97,3608.89 4295.08,3621 ; v1(4252.08,3327.39) UD1.V1@4273.29,3327.39 ; v1(4253,3705.64) 4254.72,3705.64 4260.33,3711.25 4273.29,3711.25 v1(4284.99,3699.55) 4287.12,3697.43 4293.03,3697.43 UD1.D2@4304.79,3685.66 ; v1(4255.74,3283.64) 4258.7,3283.64 4266.13,3276.21 4278.29,3276.21 4288.08,3286 v1(4290.08,3286) 4290.08,3287.08 UD1.W2@4304.79,3301.8 ; v1(4258.7,3654.27) 4264.5,3660.07 UD1.E1@4273.29,3660.07 ; v1(4260.4,3365.68) UD1.T1@4273.29,3378.57 ; v1(4290.37,3450.37) 4295.34,3455.34 UD1.N2@4304.79,3455.34 ; v1(4291,3540) 4294.36,3536.64 4300.27,3536.64 UD1.K2@4304.79,3532.12 ; v1(4320.19,3619.59) 4330.89,3608.89 UD1.G3@4336.28,3608.89 ; v1(4320.65,3567.3) 4326.69,3567.3 UD1.J3@4336.28,3557.71 ; v1(4336,3206) 4336.28,3206.28 UD1.AB3@4336.28,3225.03 ; UD1.A3@4336.28,3762.44 4338.08,3764.24 v1(4338.08,3781) ; UD1.P3@4336.33,3429.75 4353.08,3413 4353.08,3396.9 v1(4352,3395.82) 4351.89,3395.71 4351.89,3394.18 4336.28,3378.57 4352.25,3362.6 4352.25,3342.26 4352,3342.01 v1(4352,3339) 4352,3317.58 UD1.W4@4367.78,3301.8 ; v1(4352.08,3672) 4354.12,3672 4381.12,3699 v1(4382.08,3699) 4383.06,3699.98 4388.01,3699.98 4409.62,3721.59 v1(4415.99,3721.59) ; UD1.N4@4367.78,3455.34 4378.12,3445 4383,3445 4383.52,3444.48 v1(4383.76,3444.48) ; UD1.K4@4367.78,3532.12 4368.2,3532.12 4376.08,3540 4381,3540 v1(4383,3542) ; 4385.85,3392 4399.28,3378.57 4406.37,3378.57 v1(4412.82,3385.03) ; UD1.AB5@4399.28,3225.03 4399.28,3223.98 4407.25,3204.75 v1(4408,3204) ; UD1.Y5@4399.28,3276.21 4406.58,3268.91 v1(4419,3268.91) ; UD1.V5@4399.28,3327.39 4411.47,3327.39 4419.08,3335 4419.75,3335 v1(4420,3335.25) ; UD1.G5@4399.28,3608.89 4416.19,3608.89 v1(4421.08,3604) 4424,3604 4466.3,3561.7 v1(4466.3,3556) ; UD1.E5@4399.28,3660.07 v1(4417.65,3678.44) ; v1(4471.08,3660.07) UD1.E8@4493.75,3660.07 ; v1(4476.34,3320.97) 4482.76,3327.39 UD1.V8@4493.75,3327.39 ; v1(4476.95,3720.78) 4486.48,3711.25 UD1.C8@4493.75,3711.25 ; v1(4482,3287.96) UD1.Y8@4493.75,3276.21 ; v1(4484.08,3208) 4493.75,3217.67 UD1.AB8@4493.75,3225.03 ; UD1.T8@4493.75,3378.57 v1(4508.67,3363.65) ; UD1.G8@4493.75,3608.89 4506.86,3622 v1(4509.08,3622) ; v1(4509.08,3700) 4523.42,3685.66 UD1.D9@4525.26,3685.66 ; UD1.N9@4525.25,3455.34 4538.59,3442 v1(4541.08,3442) 4553.33,3429.75 UD1.P10@4556.76,3429.75 ; UD1.K9@4525.25,3532.12 4536.13,3543 4539.93,3543 v1(4542.48,3545.55) ; v1(4542,3288) 4539.05,3288 4525.25,3301.8 4527.45,3304 4532.08,3304 v1(4543.08,3315) 4540.17,3317.91 4540.17,3341.47 4540.17,3361.98 v1(4542.2,3364.01) 4542.2,3364.8 UD1.T10@4556.24,3378.84 ; v1(4542.08,3645) 4542,3644.92 4542,3642.92 4540.69,3641.61 4540.69,3624.96 4544.35,3621.3 4556.76,3608.89 4562,3608.89 v1(4572.94,3597.95) 4574.41,3596.48 v1@4580.13,3596.48 ; UD1.J10@4556.24,3557.98 4581.83,3532.39 UD1.K11@4587.73,3532.39 4591.39,3532.39 v1(4603,3544) 4616.98,3557.98 UD1.J12@4619.23,3557.98 ; UD1.AB10@4556.76,3225.03 4571.79,3210 v1(4573.08,3210) ; UD1.A10@4556.76,3762.43 4558.68,3762.43 v1(4571.35,3749.76) ; UD1.W11@4588.25,3301.8 4591.68,3301.8 v1(4603.62,3289.86) 4606.1,3289.86 4646,3249.96 v1(4646,3229) ; UD1.D11@4588.24,3685.66 4602.58,3700 v1(4605,3700) 4606.68,3701.68 4610.18,3701.68 4632.52,3724.02 v1(4636.15,3724.02) 4644.63,3732.5 C7.1@4663,3732.5 ; v1(4603.08,3473) 4603.08,3470.18 4588.24,3455.34 v1(4601.6,3441.98) 4603.24,3440.34 4608.91,3440.34 UD1.P12@4619.23,3430.02 4642.02,3430.02 v1(4645,3433) 4656.5,3421.5 C12.1@4664,3421.5 C4.1@4664,3396.5 ; v1(4603.65,3598.21) v1@4605.41,3598.21 ; v1@4603.68,3596.48 v1@4605.41,3598.21 ; v1(4605.08,3510) 4617.08,3498 C8.2@4664,3498 C1.2@4664,3526 ; v1(4606.71,3391.75) 4619.23,3379.23 UD1.T12@4619.23,3378.84 ; UD1.V12@4619.75,3327.39 4636.39,3327.39 v1(4637,3328) 4639.5,3325.5 C11.1@4664,3325.5 C18.1@4664,3299.5 ; UD1.E12@4619.75,3660.07 4638.15,3660.07 v1(4643.08,3665) 4659.58,3681.5 C17.1@4663,3681.5 ; v1(4630.1,3210.1) 4646,3226 v1(4646,3229) ; C9.1@4663,3627.5 4664,3626.5 C3.1@4664,3597.5 4655.12,3606.38 v1(4638.39,3606.38) 4635.88,3608.89 4616.09,3608.89 v1@4605.41,3598.21 ; C2.2@4664,3229 v1(4646,3229) ; U1.AA22@3703.59,3556.92 3714.2,3567.53 v1(3717.55,3567.53) ; U1.AA22@3703.59,3556.92 3689.68,3570.84 3703.59,3584.75 3703.6,3581.48 v1(3717.55,3567.53) ; U1.AA22@3703.59,3556.91 3714.05,3546.46 v1(3714.05,3541.33) ; U1.AA22@3703.59,3556.91 3689.68,3543 3689.68,3536.01 v1(3698.49,3527.2) 3712.62,3541.33 v1(3714.05,3541.33) ; v1(3714.05,3541.33) 3724.69,3551.97 3729.49,3551.97 v1(3731.3,3553.78) v1(3717.55,3567.53) ; U1.AE19@3717.51,3459.48 U1.AE20@3731.44,3473.41 ; U1.AE19@3717.51,3459.48 3703.6,3445.57 v1(3716.85,3432.32) 3731.77,3447.24 ; U1.AE19@3717.51,3459.48 3729.75,3447.24 3731.77,3447.24 ; U1.AE20@3731.44,3473.4 v1@3743.72,3461.12 ; U1.AE20@3731.43,3473.41 3717.52,3487.32 U1.AD21@3731.44,3501.24 ; U1.AE20@3731.44,3473.41 U1.AE21@3745.35,3487.32 ; U1.AD21@3731.44,3501.24 U1.AD22@3745.36,3515.16 ; U1.AD21@3731.44,3501.23 U1.AE21@3745.35,3487.32 ; 3731.77,3447.24 v1(3743.72,3459.19) v1@3743.72,3461.12 ; 3733.3,3640.45 3732.37,3641.38 3745.35,3654.36 3745.35,3652.49 3733.3,3640.45 ; 3733.3,3640.45 3745.36,3628.39 U1.Y26@3745.36,3626.52 ; 3733.3,3640.45 3732.37,3639.51 U1.Y26@3745.36,3626.52 ; v1@3743.72,3461.12 3745.5,3461.12 3758.57,3474.19 v1(3772.74,3488.36) ; U1.AE21@3745.35,3487.32 U1.AE22@3759.28,3501.25 ; U1.AD22@3745.37,3515.16 U1.AE22@3759.28,3501.25 ; U1.AD22@3745.36,3515.16 3755.74,3525.54 3755.74,3527.22 v1(3757.69,3529.17) 3757.69,3530.66 U1.AE23@3773.19,3515.16 ; U1.AE22@3759.28,3501.25 U1.AE23@3773.19,3515.16 ; U1.AE22@3759.28,3501.23 3772.15,3488.36 v1(3772.74,3488.36) ; v1(3772.74,3488.36) 3773.75,3489.37 3773.75,3490.84 3783.75,3500.84 3786.71,3500.84 3786.71,3501.64 ; U1.AE23@3773.19,3515.16 U1.AE24@3787.11,3529.08 ; U1.AE23@3773.19,3515.16 3786.71,3501.64 ; 3786.71,3501.64 3786.71,3502.34 v1(3800.28,3515.91) U1.AE24@3787.11,3529.08 ; U1.AE24@3787.11,3529.08 U1.AE25@3801.03,3543 ; U1.AE25@3801.03,3543 3814.95,3556.92 3820.42,3551.45 3820.42,3531.88 v1(3815.84,3527.3) ; U1.AE25@3801.03,3543 3812.56,3531.47 3815.84,3531.47 v1(3815.84,3527.3)
  Top Layer w15: v1(4014.46,3630.28) 4032.32,3630.28 4048.44,3614.16 C5.1@4095.52,3614.16
  Inner1 w3: 4555,3432 4556,3431 4581,3431 4582,3432
  Inner2 w10: v1(3801,3684) 3801,3703.79 v1@3881.68,3784.47
  Bottom Layer w8: C16.1@4232,3705.5 4232.14,3705.64 v1(4253,3705.64) ; C13.1@4331.5,3366 4352,3345.5 v1(4352,3339) ; v1(4338.08,3781) 4341,3783.92 C14.2@4341,3801
  Bottom Layer w10: C19.2@4247,3598 4247,3612.06 v1(4251.48,3616.54) ; v1(4252.08,3327.39) 4257.98,3333.29 C22.1@4271.09,3333.29 ; v1(4291,3540) 4294,3537 C15.2@4294,3516 ; C10.1@4292.13,3620.87 4298.83,3614.17 4314.77,3614.17 v1(4320.19,3619.59) ; C26.1@4395.5,3723 4414.58,3723 v1(4415.99,3721.59) 4437.91,3721.59 C25.1@4439,3720.5 ; v1(4408,3204) 4412.51,3208.51 C21.1@4412.51,3221.29 ; v1(4412.82,3385.03) 4432.59,3404.8 C20.1@4432.59,3405.33 ; v1(4419,3268.91) 4442.59,3268.91 C24.1@4443,3268.5 ; C23.1@4502,3667.5 4502,3677.43 4502.08,3677.51 4502.08,3693 v1(4509.08,3700) ; v1(4603.08,3473) 4608.23,3478.15 4608.23,3506.85 v1(4605.08,3510)
  other v1: 4548.6,3096.8 4015,3117 3974,3158 3789.13,3360.71 3686.44,3625.51
SAA0: U1.AJ33 UD1.H2 | length 366.3
  Top Layer w3: U1.AJ33@3968.07,3598.68 3985.52,3616.13 4026.95,3616.13
  Top Layer w4.5: 4026.95,3616.13 4051.58,3591.5 4208.97,3591.5 4227.74,3572.73 4281.81,3572.73 4292.38,3583.3 UD1.H2@4304.79,3583.3
SAA1: U1.AJ32 UD1.J2 | length 384.9
  Top Layer w3: U1.AJ32@3954.15,3584.76 3968.04,3584.76 3985.28,3602 4023.07,3602
  Top Layer w4.5: 4023.07,3602 4048.07,3577 4202.96,3577 4226.96,3553 4262.22,3553 4268.08,3547.14 4277.67,3547.14 4287.76,3557.23 4288.25,3557.23 4288.73,3557.71 UD1.J2@4304.79,3557.71
SAA2: U1.AG30 UD1.H9 | length 728.3
  Top Layer w4: U1.AG30@3898.47,3584.76 3900.21,3586.5 v1(3927.3,3586.5) ; UD1.H9@4525.25,3583.3 v1(4541.01,3599.05)
  Inner2 w4.5: v1(3927.3,3586.5) 3929.05,3586.5 3955.55,3613 4051,3613 4072.36,3634.36 4332.49,3634.36 4332.68,3634.55 4358.45,3634.55 4366.37,3626.63 4366.37,3618.16 4373.53,3611 4393.06,3611 4418.81,3585.25 4418.99,3585.25 4427.33,3576.91 4427.33,3576.73 4432.76,3571.3 4513.26,3571.3 4517.56,3575.6 4517.78,3575.6 4528.49,3586.31 4528.49,3586.53 v1(4541.01,3599.05)
SAA3: U1.AG29 UD1.H10 | length 747.7
  Top Layer w4: U1.AG29@3884.55,3570.84 3886.01,3569.38 3912.08,3569.38 v1@3914.12,3571.42
  Top Layer w4.5: v1(4543.53,3572.03) 4545.49,3572.03 UD1.H10@4556.76,3583.3
  Inner2 w4.5: v1(3914.15,3571.42) 3914.48,3571.42 3916.7,3569.2 3930.84,3569.2 3964.64,3603 4063.98,3603 4143.84,3523.14 4496.6,3523.14 4543.53,3570.05 v1(4543.53,3572.03)
SAA4: U1.AJ30 UD1.H11 | length 752.7
  Top Layer w4: v1(4575.45,3570.51) UD1.H11@4588.24,3583.3
  Top Layer w4.5: U1.AJ30@3926.31,3556.92 v1(3939.14,3544.09)
  Inner2 w3: 3939.14,3560.62 3949.92,3571.4 4075.07,3571.4
  Inner2 w4.5: v1(3939.14,3544.09) 3939.14,3560.62 ; 4075.07,3571.4 4137.83,3508.64 4526.43,3508.64 4575.45,3557.66 v1(4575.45,3570.51)
SAA5: U1.AJ31 UD1.J11 | length 753.3
  Top Layer w4.5: U1.AJ31@3940.22,3570.84 3952.91,3558.15 v1(3955.06,3558.15) ; UD1.J11@4588.25,3557.71 4600.54,3570 v1(4605.08,3570)
  Inner2 w3: v1(3955.06,3558.15) 3956.81,3559.9 4062.01,3559.9
  Inner2 w4.5: 4062.01,3559.9 4127.77,3494.14 4532.44,3494.14 4605.08,3566.78 v1(4605.08,3570)
SAB0: U1.AJ25 UD1.R2 | length 512.6
  Top Layer w4.5: U1.AJ25@3856.71,3487.32 3856.71,3489.5 v1(3868.53,3501.32) ; v1(4164.08,3403.77) 4210.89,3403.77 4222.12,3415 4293.95,3415 UD1.R2@4304.79,3404.16
  Inner2 w3: v1(3868.53,3501.32) 3896.68,3501.32 3927,3471 3943,3471 3963.87,3450.13 3996.13,3450.13 4033.46,3451
  Inner2 w4.5: 4033.46,3451 4079.76,3404.7 4115.89,3404.7 4125.89,3394.7 4155.01,3394.7 v1(4164.08,3403.77)
SAB1: U1.AH25 UD1.P2 | length 536.9
  Top Layer w4.5: U1.AH25@3842.79,3501.24 3842.79,3505.28 v1(3853.68,3516.17) ; v1(4135.4,3409.4) 4137.4,3409.4 4148,3420 4175,3420 4191.25,3436.25 4218.75,3436.25 4223,3432 4256,3432 4266,3442 4279,3442 4291.25,3429.75 UD1.P2@4304.79,3429.75
  Inner2 w3: v1(3853.68,3516.17) 3877.83,3516.17 3886,3508 3899,3508 3928.59,3478.41 4026.56,3478.41
  Inner2 w4.5: 4026.56,3478.41 4085.47,3419.5 4124.5,3419.5 4134.6,3409.4 v1(4135.4,3409.4)
SAB2: U1.AL25 UD1.R9 | length 758.5
  Top Layer w4: v1(4510.12,3389.02) UD1.R9@4525.25,3404.16
  Top Layer w4.5: U1.AL25@3884.55,3459.48 v1(3897.4,3472.33)
  Inner2 w3: v1(3897.4,3472.33) 3920.2,3449.53 3944.46,3449.53 3959.99,3434 3997,3434 4001,3430
  Inner2 w4.5: 4001,3430 4013.28,3430 4119.28,3324 4229.88,3324 4240.74,3313.14 4276.52,3313.14 4284.38,3321 4457.1,3321 4482.08,3345.98 4482.08,3360.98 v1(4510.12,3389.02)
SAB3: U1.AK25 UD1.R10 | length 821.8
  Top Layer w4.5: U1.AK25@3870.63,3473.4 3870.63,3475.13 v1(3882.68,3487.18) ; v1(4461.49,3348.55) 4461.49,3398.39 4480.1,3417 4543.92,3417 UD1.R10@4556.76,3404.16
  Inner2 w3: v1(3882.68,3487.18) 3902.26,3487.18 3926.44,3463 3941.01,3463 3963.01,3441 4001,3441 4004,3438 4019,3438
  Inner2 w4.5: 4019,3438 4025.79,3438 4116.29,3347.5 4311.42,3347.5 4316.92,3353 4363,3353 4371,3345 4403,3345 4408,3350 4460.04,3350 v1(4461.49,3348.55)
SAB4: U1.AJ27 UD1.R11 | length 810.6
  Top Layer w4: U1.AJ27@3884.55,3515.16 3895.01,3525.62 3897.11,3525.62 v1(3897.79,3526.31) ; v1(4572,3418) 4574.41,3418 UD1.R11@4588.25,3404.16
  Inner2 w3: v1(3897.79,3526.31) 3917.62,3526.31 3944.93,3499
  Inner2 w4.5: 3944.93,3499 3989.3,3499 4004.5,3514.2 4033.88,3514.2 4098.08,3450 4202.3,3450 4223,3429.3 4339.7,3429.3 4344.4,3424.6 4359.6,3424.6 4370,3435 4370,3453 4376,3459 4501.99,3459 4542.99,3418 v1(4572,3418)
SAB5: U1.AL29 UD1.P11 | length 704
  Top Layer w4: v1(4573.33,3444.67) UD1.P11@4588.25,3429.75
  Top Layer w4.5: U1.AL29@3940.22,3515.16 v1(3953.58,3528.52)
  Inner2 w4.5: v1(3953.58,3528.52) 3965.06,3540 4037.7,3540 4048.7,3529 4061.2,3529 4111.08,3479.12 4538.88,3479.12 v1(4573.33,3444.67)
SCKE0-A: U1.AM31 UD1.J4 | length 429.3
  Top Layer w3: U1.AM31@3981.99,3529.08 3986.07,3525 4000.01,3525 4005.75,3519.26 4005.95,3519.26 4013.55,3511.66 4034.34,3511.66
  Top Layer w4.5: 4034.34,3511.66 4040,3506 4124.25,3506 4148.62,3530.37 4201.45,3530.37 v1(4210.08,3539) ; v1(4351,3545) 4355.18,3545 4367.78,3557.6 UD1.J4@4367.78,3557.71
  Inner2 w4.5: v1(4210.08,3539) 4231.08,3560 4301,3560 4308,3553 4329.21,3553 4337.21,3545 v1(4351,3545)
SCKE0-B: U1.AN27 UD1.P4 | length 517.8
  Top Layer w3: U1.AN27@3940.22,3459.48 3965.7,3434 3986.5,3434 4009.51,3411
  Top Layer w4: UD1.P4@4367.78,3429.75 4372.33,3429.75 v1(4384.08,3418)
  Top Layer w4.5: 4009.51,3411 4015.68,3411 4026.35,3400.33 4070.79,3400.33 4095.62,3375.5 4138.58,3375.5 v1(4142.58,3379.5)
  Inner2 w4.5: v1(4142.58,3379.5) 4143.08,3379 4232.08,3379 4250.32,3397.24 4327.34,3397.24 4342.5,3412.4 4378.48,3412.4 v1(4384.08,3418)
SCKE1-A: U1.AL31 UD1.J5 | length 525
  Top Layer w3: U1.AL31@3968.06,3543 3982.02,3543 3991.85,3533.18 4000.03,3533.18 4005.75,3538.9 4013.9,3538.9 4019.66,3533.14 4041.94,3533.14
  Top Layer w4: UD1.J5@4399.28,3557.71 4399.79,3557.71 v1(4413.08,3571)
  Top Layer w4.5: 4041.94,3533.14 4043.83,3531.25 4115.25,3531.25 4145,3561 v1(4154,3561)
  Inner2 w4.5: v1(4154,3561) 4169.8,3545.2 4195.27,3545.2 4222.47,3572.4 4302.48,3572.4 4312.08,3582 4328,3582 4350.5,3559.5 4360.5,3559.5 4364,3556 4398.08,3556 v1(4413.08,3571)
